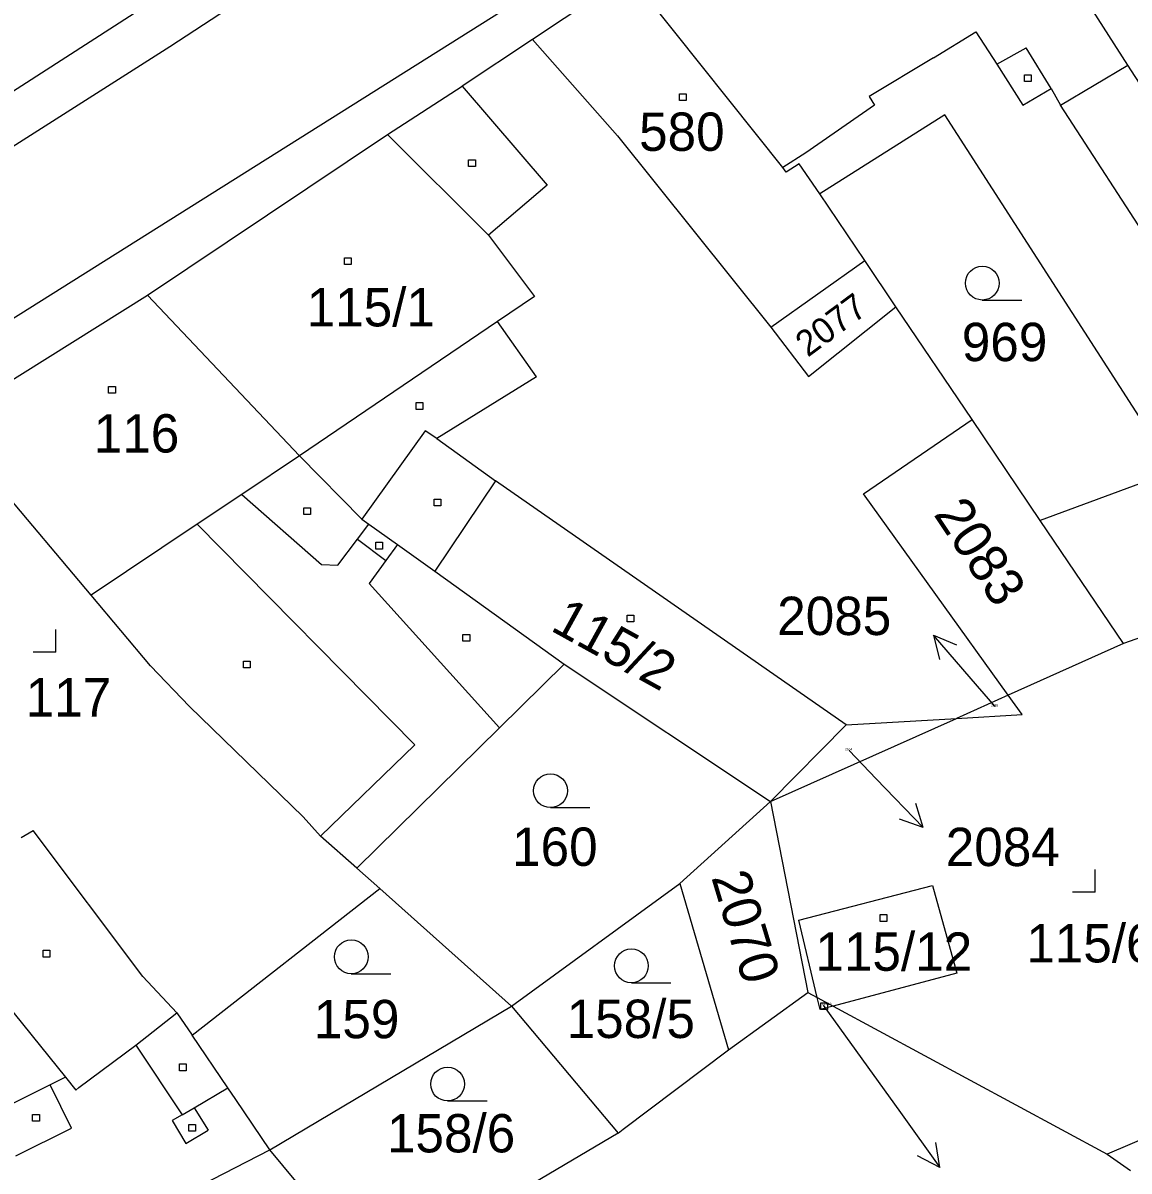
# Model space of a CAD drawing. Extents: x -711879 to -711361, y -1048782 to -1048177.
# Drawn here: x -711718.9 to -711669.9, y -1048619.6 to -1048568.8 of the extents above; entities that cross this region are included whole.
import ezdxf

# ---------------------------------------------------------------- set-up
doc = ezdxf.new("R2010")
doc.units = 0
for name, color, linetype in [('Vrstva 1', 7, 'Continuous'), ('Vrstva 13', 7, 'Continuous'), ('Vrstva 14', 7, 'Continuous'), ('Vrstva 15', 7, 'Continuous'), ('Vrstva 16', 7, 'Continuous'), ('Vrstva 2', 7, 'Continuous'), ('Vrstva 23', 7, 'Continuous'), ('Vrstva 25', 7, 'Continuous'), ('Vrstva 46', 7, 'Continuous')]:
    doc.layers.add(name, color=color, linetype=linetype)

msp = doc.modelspace()

# ---------------------------------------------------------------- linework, layer by layer
at = {"layer": 'Vrstva 1'}
for p, q in [((-711701.7, -1048560.4), (-711721.23, -1048572.99)), ((-711669.91, -1048570.62), (-711672.81, -1048566.11)), ((-711692.02, -1048566.63), (-711696.32, -1048569.48)), ((-711685.22, -1048575.16), (-711692.02, -1048566.63)), ((-711696.32, -1048569.48), (-711699.43, -1048571.55)), ((-711696.32, -1048569.48), (-711692.54, -1048573.75)), ((-711665.72, -1048577.15), (-711669.91, -1048570.62)), ((-711702.75, -1048573.69), (-711699.43, -1048571.55)), ((-711678.03, -1048572.83), (-711683.58, -1048576.33)), ((-711667.86, -1048588.61), (-711678.03, -1048572.83)), ((-711713.38, -1048580.81), (-711702.75, -1048573.69)), ((-711692.54, -1048573.75), (-711685.74, -1048582.24)), ((-711685.06, -1048575.36), (-711685.22, -1048575.16)), ((-711684.49, -1048574.99), (-711685.06, -1048575.36)), ((-711683.58, -1048576.33), (-711684.49, -1048574.99)), ((-711681.58, -1048579.28), (-711683.58, -1048576.33)), ((-711685.74, -1048582.24), (-711681.58, -1048579.28)), ((-711680.2, -1048581.33), (-711681.58, -1048579.28)), ((-711722.36, -1048586.43), (-711713.38, -1048580.81)), ((-711713.38, -1048580.81), (-711706.64, -1048587.93)), ((-711684.08, -1048584.42), (-711680.2, -1048581.33)), ((-711676.82, -1048586.33), (-711680.2, -1048581.33)), ((-711685.74, -1048582.24), (-711684.08, -1048584.42)), ((-711681.64, -1048589.62), (-711676.82, -1048586.33)), ((-711673.81, -1048590.81), (-711676.82, -1048586.33)), ((-711715.89, -1048594.11), (-711722.36, -1048586.43)), ((-711701.07, -1048586.83), (-711703.88, -1048590.74)), ((-711700.56, -1048587.17), (-711701.07, -1048586.83)), ((-711700.56, -1048587.17), (-711697.96, -1048589.04)), ((-711706.64, -1048587.93), (-711703.88, -1048590.74)), ((-711667.86, -1048588.61), (-711673.81, -1048590.81)), ((-711682.4, -1048599.86), (-711697.96, -1048589.04)), ((-711675.22, -1048598.54), (-711681.64, -1048589.62)), ((-711703.88, -1048590.74), (-711703.57, -1048590.96)), ((-711670.11, -1048596.26), (-711673.81, -1048590.81)), ((-711703.57, -1048590.96), (-711702.3, -1048591.87)), ((-711702.3, -1048591.87), (-711700.65, -1048593.05)), ((-711657.67, -1048591.88), (-711670.11, -1048596.26)), ((-711700.65, -1048593.05), (-711694.91, -1048597.17)), ((-711713.25, -1048597.25), (-711715.89, -1048594.11)), ((-711670.11, -1048596.26), (-711675.22, -1048598.54)), ((-711711.52, -1048599.04), (-711713.25, -1048597.25)), ((-711694.91, -1048597.17), (-711697.78, -1048599.99)), ((-711694.91, -1048597.17), (-711685.76, -1048603.26)), ((-711675.22, -1048598.54), (-711677.52, -1048599.58)), ((-711674.6, -1048599.4), (-711675.22, -1048598.54)), ((-711706.49, -1048603.94), (-711711.52, -1048599.04)), ((-711685.76, -1048603.26), (-711677.52, -1048599.58)), ((-711682.4, -1048599.86), (-711677.52, -1048599.58)), ((-711677.52, -1048599.58), (-711674.6, -1048599.4)), ((-711697.78, -1048599.99), (-711704.11, -1048606.21)), ((-711685.76, -1048603.26), (-711682.4, -1048599.86)), ((-711689.78, -1048606.89), (-711685.76, -1048603.26)), ((-711685.76, -1048603.26), (-711684.1, -1048611.72)), ((-711705.71, -1048604.79), (-711706.49, -1048603.94)), ((-711718.99, -1048604.85), (-711718.45, -1048604.54)), ((-711713.59, -1048611.01), (-711718.45, -1048604.54)), ((-711704.11, -1048606.21), (-711705.71, -1048604.79)), ((-711703.09, -1048607.12), (-711704.11, -1048606.21)), ((-711711.41, -1048613.62), (-711703.09, -1048607.12)), ((-711703.09, -1048607.12), (-711697.25, -1048612.33)), ((-711697.25, -1048612.33), (-711689.78, -1048606.89)), ((-711689.78, -1048606.89), (-711687.63, -1048614.26)), ((-711683.69, -1048611.94), (-711684.5, -1048608.51)), ((-711713.59, -1048611.01), (-711712.08, -1048612.63)), ((-711687.63, -1048614.26), (-711684.1, -1048611.72)), ((-711684.1, -1048611.72), (-711683.69, -1048611.94)), ((-711683.56, -1048612.48), (-711683.69, -1048611.94)), ((-711683.69, -1048611.94), (-711682.98, -1048612.33)), ((-711713.9, -1048614.06), (-711712.08, -1048612.63)), ((-711712.08, -1048612.63), (-711711.41, -1048613.62)), ((-711707.96, -1048618.7), (-711697.25, -1048612.33)), ((-711697.25, -1048612.33), (-711692.51, -1048617.95)), ((-711682.98, -1048612.33), (-711683.56, -1048612.48)), ((-711682.98, -1048612.33), (-711670.84, -1048618.89)), ((-711709.83, -1048615.95), (-711711.41, -1048613.62)), ((-711716.43, -1048615.94), (-711713.9, -1048614.06)), ((-711692.29, -1048617.78), (-711687.63, -1048614.26)), ((-711660.3, -1048614.41), (-711670.84, -1048618.89)), ((-711717.7, -1048615.82), (-711720.7, -1048617.31)), ((-711717.02, -1048615.48), (-711717.7, -1048615.82)), ((-711717.02, -1048615.48), (-711716.56, -1048616.05)), ((-711716.56, -1048616.05), (-711716.43, -1048615.94)), ((-711709.47, -1048616.47), (-711709.83, -1048615.95)), ((-711707.96, -1048618.7), (-711709.47, -1048616.47)), ((-711692.51, -1048617.95), (-711692.29, -1048617.78)), ((-711692.51, -1048617.95), (-711703.27, -1048624.31)), ((-711719.96, -1048624.83), (-711707.96, -1048618.7)), ((-711703.27, -1048624.31), (-711707.96, -1048618.7)), ((-711670.84, -1048618.89), (-711669.8, -1048619.61))]:
    msp.add_line(p, q, dxfattribs=at)
msp.add_lwpolyline([(-711684.5, -1048608.51), (-711678.58, -1048606.98), (-711677.5, -1048610.86), (-711682.98, -1048612.33)], dxfattribs=at)
at = {"layer": 'Vrstva 13'}
for p, q in [((-711675.8, -1048599.05), (-711676.58, -1048598.15)), ((-711682.28, -1048600.99), (-711681.07, -1048602.25)), ((-711683.42, -1048612.28), (-711680, -1048617.04))]:
    msp.add_line(p, q, dxfattribs=at)
at = {"layer": 'Vrstva 16'}
for p, q in [((-711676.58, -1048598.15), (-711678.541, -1048595.88)), ((-711678.541, -1048595.88), (-711678.266, -1048596.963)), ((-711678.541, -1048595.88), (-711677.509, -1048596.309)), ((-711681.07, -1048602.25), (-711678.993, -1048604.415)), ((-711678.993, -1048604.415), (-711679.324, -1048603.347)), ((-711678.993, -1048604.415), (-711680.046, -1048604.039)), ((-711680, -1048617.04), (-711678.25, -1048619.477)), ((-711678.25, -1048619.477), (-711678.427, -1048618.373)), ((-711678.25, -1048619.477), (-711679.239, -1048618.956))]:
    msp.add_line(p, q, dxfattribs=at)
at = {"layer": 'Vrstva 2'}
for p, q in [((-711712.4, -1048569.8), (-711692.52, -1048556.74)), ((-711687.47, -1048561.81), (-711745.53, -1048598.31)), ((-711678.53, -1048570.29), (-711676.66, -1048569.14)), ((-711676.66, -1048569.14), (-711675.72, -1048570.58)), ((-711736.24, -1048584.93), (-711712.4, -1048569.8)), ((-711675.72, -1048570.58), (-711674.43, -1048569.85)), ((-711673.31, -1048571.66), (-711674.43, -1048569.85)), ((-711678.53, -1048570.29), (-711681.39, -1048572.01)), ((-711675.72, -1048570.58), (-711674.57, -1048572.4)), ((-711672.9, -1048572.39), (-711669.91, -1048570.62)), ((-711699.43, -1048571.55), (-711695.66, -1048575.94)), ((-711681.39, -1048572.01), (-711681.15, -1048572.39)), ((-711674.57, -1048572.4), (-711673.31, -1048571.66)), ((-711673.31, -1048571.66), (-711672.9, -1048572.39)), ((-711681.15, -1048572.39), (-711684.19, -1048574.5)), ((-711668.28, -1048579.53), (-711672.9, -1048572.39)), ((-711698.26, -1048578.16), (-711702.75, -1048573.69)), ((-711684.19, -1048574.5), (-711685.22, -1048575.16)), ((-711695.66, -1048575.94), (-711698.26, -1048578.16)), ((-711698.26, -1048578.16), (-711696.23, -1048580.87)), ((-711696.23, -1048580.87), (-711697.86, -1048581.98)), ((-711697.86, -1048581.98), (-711706.64, -1048587.93)), ((-711696.14, -1048584.43), (-711697.86, -1048581.98)), ((-711696.14, -1048584.43), (-711700.56, -1048587.17)), ((-711706.64, -1048587.93), (-711709.21, -1048589.65)), ((-711697.96, -1048589.04), (-711700.65, -1048593.05)), ((-711709.21, -1048589.65), (-711711.19, -1048590.97)), ((-711709.21, -1048589.65), (-711705.67, -1048592.75)), ((-711711.19, -1048590.97), (-711715.89, -1048594.11)), ((-711701.54, -1048600.75), (-711711.19, -1048590.97)), ((-711704.08, -1048591.63), (-711703.57, -1048590.96)), ((-711704.94, -1048592.78), (-711704.08, -1048591.63)), ((-711704.08, -1048591.63), (-711702.82, -1048592.58)), ((-711702.3, -1048591.87), (-711702.82, -1048592.58)), ((-711705.67, -1048592.75), (-711704.94, -1048592.78)), ((-711702.82, -1048592.58), (-711703.56, -1048593.59)), ((-711703.56, -1048593.59), (-711697.78, -1048599.99)), ((-711705.71, -1048604.79), (-711701.54, -1048600.75)), ((-711721.21, -1048610.29), (-711717.02, -1048615.48)), ((-711713.9, -1048614.06), (-711711.85, -1048617.14)), ((-711716.76, -1048617.74), (-711717.7, -1048615.82)), ((-711711.32, -1048616.83), (-711709.83, -1048615.95)), ((-711711.85, -1048617.14), (-711711.32, -1048616.83)), ((-711711.32, -1048616.83), (-711710.7, -1048617.82)), ((-711711.85, -1048617.14), (-711712.29, -1048617.39)), ((-711712.29, -1048617.39), (-711711.69, -1048618.41)), ((-711719.23, -1048618.96), (-711716.76, -1048617.74)), ((-711711.69, -1048618.41), (-711710.7, -1048617.82))]:
    msp.add_line(p, q, dxfattribs=at)
at = {"layer": 'Vrstva 23'}
for p, q in [((-711676.37, -1048581.03), (-711674.62, -1048581.03)), ((-711717.45, -1048596.64), (-711717.45, -1048595.64)), ((-711717.45, -1048596.64), (-711718.45, -1048596.64)), ((-711695.52, -1048603.53), (-711693.77, -1048603.53)), ((-711671.37, -1048607.27), (-711671.37, -1048606.27)), ((-711671.37, -1048607.27), (-711672.37, -1048607.27)), ((-711704.35, -1048610.89), (-711702.6, -1048610.89)), ((-711691.93, -1048611.29), (-711690.18, -1048611.29)), ((-711700.08, -1048616.53), (-711698.33, -1048616.53))]:
    msp.add_line(p, q, dxfattribs=at)
for centre in [(-711676.37, -1048580.28), (-711695.52, -1048602.78), (-711704.35, -1048610.14), (-711691.93, -1048610.54), (-711700.08, -1048615.78)]:
    msp.add_circle(centre, 0.75, dxfattribs=at)
at = {"layer": 'Vrstva 25'}
for p, q in [((-711674.5, -1048571.05), (-711674.2, -1048571.05)), ((-711674.5, -1048571.35), (-711674.5, -1048571.05)), ((-711674.2, -1048571.05), (-711674.2, -1048571.35)), ((-711674.2, -1048571.35), (-711674.5, -1048571.35)), ((-711689.8, -1048571.89), (-711689.5, -1048571.89)), ((-711689.8, -1048572.19), (-711689.8, -1048571.89)), ((-711689.5, -1048571.89), (-711689.5, -1048572.19)), ((-711689.5, -1048572.19), (-711689.8, -1048572.19)), ((-711699.15, -1048574.82), (-711698.85, -1048574.82)), ((-711699.15, -1048575.12), (-711699.15, -1048574.82)), ((-711698.85, -1048575.12), (-711699.15, -1048575.12)), ((-711698.85, -1048574.82), (-711698.85, -1048575.12)), ((-711704.65, -1048579.16), (-711704.35, -1048579.16)), ((-711704.65, -1048579.46), (-711704.65, -1048579.16)), ((-711704.35, -1048579.16), (-711704.35, -1048579.46)), ((-711704.35, -1048579.46), (-711704.65, -1048579.46)), ((-711715.11, -1048584.86), (-711714.81, -1048584.86)), ((-711715.11, -1048585.16), (-711715.11, -1048584.86)), ((-711714.81, -1048585.16), (-711715.11, -1048585.16)), ((-711714.81, -1048584.86), (-711714.81, -1048585.16)), ((-711701.48, -1048585.58), (-711701.18, -1048585.58)), ((-711701.48, -1048585.88), (-711701.48, -1048585.58)), ((-711701.18, -1048585.58), (-711701.18, -1048585.88)), ((-711701.18, -1048585.88), (-711701.48, -1048585.88)), ((-711700.68, -1048589.86), (-711700.38, -1048589.86)), ((-711700.68, -1048590.16), (-711700.68, -1048589.86)), ((-711700.38, -1048589.86), (-711700.38, -1048590.16)), ((-711706.46, -1048590.24), (-711706.16, -1048590.24)), ((-711706.46, -1048590.54), (-711706.46, -1048590.24)), ((-711706.16, -1048590.24), (-711706.16, -1048590.54)), ((-711700.38, -1048590.16), (-711700.68, -1048590.16)), ((-711706.16, -1048590.54), (-711706.46, -1048590.54)), ((-711703.26, -1048591.77), (-711702.96, -1048591.77)), ((-711703.26, -1048592.07), (-711703.26, -1048591.77)), ((-711702.96, -1048591.77), (-711702.96, -1048592.07)), ((-711702.96, -1048592.07), (-711703.26, -1048592.07)), ((-711692.12, -1048595), (-711691.82, -1048595)), ((-711692.12, -1048595.3), (-711692.12, -1048595)), ((-711691.82, -1048595), (-711691.82, -1048595.3)), ((-711691.82, -1048595.3), (-711692.12, -1048595.3)), ((-711699.4, -1048595.85), (-711699.1, -1048595.85)), ((-711699.4, -1048596.15), (-711699.4, -1048595.85)), ((-711699.1, -1048595.85), (-711699.1, -1048596.15)), ((-711699.1, -1048596.15), (-711699.4, -1048596.15)), ((-711709.13, -1048597.04), (-711708.83, -1048597.04)), ((-711709.13, -1048597.34), (-711709.13, -1048597.04)), ((-711708.83, -1048597.04), (-711708.83, -1048597.34)), ((-711708.83, -1048597.34), (-711709.13, -1048597.34)), ((-711680.9, -1048608.27), (-711680.6, -1048608.27)), ((-711680.9, -1048608.57), (-711680.9, -1048608.27)), ((-711680.6, -1048608.57), (-711680.9, -1048608.57)), ((-711680.6, -1048608.27), (-711680.6, -1048608.57)), ((-711718.02, -1048609.85), (-711717.72, -1048609.85)), ((-711718.02, -1048610.15), (-711718.02, -1048609.85)), ((-711717.72, -1048610.15), (-711718.02, -1048610.15)), ((-711717.72, -1048609.85), (-711717.72, -1048610.15)), ((-711683.53, -1048612.18), (-711683.23, -1048612.18)), ((-711683.53, -1048612.48), (-711683.53, -1048612.18)), ((-711683.23, -1048612.18), (-711683.23, -1048612.48)), ((-711683.23, -1048612.48), (-711683.53, -1048612.48)), ((-711711.97, -1048614.89), (-711711.67, -1048614.89)), ((-711711.97, -1048615.19), (-711711.97, -1048614.89)), ((-711711.67, -1048615.19), (-711711.97, -1048615.19)), ((-711711.67, -1048614.89), (-711711.67, -1048615.19)), ((-711718.48, -1048617.13), (-711718.18, -1048617.13)), ((-711718.48, -1048617.43), (-711718.48, -1048617.13)), ((-711718.18, -1048617.13), (-711718.18, -1048617.43)), ((-711718.18, -1048617.43), (-711718.48, -1048617.43)), ((-711711.56, -1048617.57), (-711711.26, -1048617.57)), ((-711711.56, -1048617.87), (-711711.56, -1048617.57)), ((-711711.26, -1048617.87), (-711711.56, -1048617.87)), ((-711711.26, -1048617.57), (-711711.26, -1048617.87))]:
    msp.add_line(p, q, dxfattribs=at)
at = {"layer": 'Vrstva 46'}
for p, q in [((-711678.53, -1048570.29), (-711678.53, -1048570.29)), ((-711675.72, -1048570.58), (-711675.72, -1048570.58)), ((-711699.43, -1048571.55), (-711699.43, -1048571.55)), ((-711672.9, -1048572.39), (-711672.9, -1048572.39)), ((-711678.03, -1048572.83), (-711678.03, -1048572.83)), ((-711702.75, -1048573.69), (-711702.75, -1048573.69)), ((-711692.54, -1048573.75), (-711692.54, -1048573.75)), ((-711684.19, -1048574.5), (-711684.19, -1048574.5)), ((-711685.06, -1048575.36), (-711685.06, -1048575.36)), ((-711698.26, -1048578.16), (-711698.26, -1048578.16)), ((-711713.38, -1048580.81), (-711713.38, -1048580.81)), ((-711696.23, -1048580.87), (-711696.23, -1048580.87)), ((-711696.14, -1048584.43), (-711696.14, -1048584.43)), ((-711700.56, -1048587.17), (-711700.56, -1048587.17)), ((-711697.96, -1048589.04), (-711697.96, -1048589.04)), ((-711681.64, -1048589.62), (-711681.64, -1048589.62)), ((-711674.28, -1048590.1), (-711674.28, -1048590.1)), ((-711673.81, -1048590.81), (-711673.81, -1048590.81)), ((-711670.11, -1048596.26), (-711670.11, -1048596.26)), ((-711713.25, -1048597.25), (-711713.25, -1048597.25)), ((-711675.22, -1048598.54), (-711675.22, -1048598.54)), ((-711711.52, -1048599.04), (-711711.52, -1048599.04)), ((-711677.52, -1048599.58), (-711677.52, -1048599.58)), ((-711674.6, -1048599.4), (-711674.6, -1048599.4)), ((-711682.4, -1048599.86), (-711682.4, -1048599.86)), ((-711685.76, -1048603.26), (-711685.76, -1048603.26)), ((-711706.49, -1048603.94), (-711706.49, -1048603.94)), ((-711718.45, -1048604.54), (-711718.45, -1048604.54)), ((-711705.71, -1048604.79), (-711705.71, -1048604.79)), ((-711703.09, -1048607.12), (-711703.09, -1048607.12)), ((-711689.78, -1048606.89), (-711689.78, -1048606.89)), ((-711713.59, -1048611.01), (-711713.59, -1048611.01)), ((-711684.1, -1048611.72), (-711684.1, -1048611.72)), ((-711683.69, -1048611.94), (-711683.69, -1048611.94)), ((-711712.08, -1048612.63), (-711712.08, -1048612.63)), ((-711697.25, -1048612.33), (-711697.25, -1048612.33)), ((-711682.98, -1048612.33), (-711682.98, -1048612.33)), ((-711711.41, -1048613.62), (-711711.41, -1048613.62)), ((-711687.63, -1048614.26), (-711687.63, -1048614.26)), ((-711717.02, -1048615.48), (-711717.02, -1048615.48)), ((-711716.56, -1048616.05), (-711716.56, -1048616.05)), ((-711716.43, -1048615.94), (-711716.43, -1048615.94)), ((-711709.47, -1048616.47), (-711709.47, -1048616.47)), ((-711716.76, -1048617.74), (-711716.76, -1048617.74)), ((-711692.29, -1048617.78), (-711692.29, -1048617.78)), ((-711692.51, -1048617.95), (-711692.51, -1048617.95)), ((-711707.96, -1048618.7), (-711707.96, -1048618.7)), ((-711670.84, -1048618.89), (-711670.84, -1048618.89))]:
    msp.add_line(p, q, dxfattribs=at)

# ---------------------------------------------------------------- texts
at = {"layer": 'Vrstva 14'}
for s, height, rotation, p in [('2077', 1.14, 36.511, (-711684.108, -1048583.592)), ('2083', 1.7, 303.5589, (-711678.558, -1048590.525)), ('2070', 1.7, 286.7937, (-711688.394, -1048606.615))]:
    msp.add_text(s, height=height, rotation=rotation, dxfattribs=at).set_placement(p)
for s, height, p in [('969', 1.7, (-711677.28, -1048583.74)), ('2085', 0.1, (-711675.974, -1048599.05)), ('2084', 0.1, (-711682.451, -1048600.99)), ('160', 1.7, (-711697.22, -1048606.11)), ('159', 1.7, (-711706.01, -1048613.75)), ('158/5', 1.7, (-711694.8, -1048613.74)), ('158/6', 1.7, (-711702.77, -1048618.81))]:
    msp.add_text(s, height=height, dxfattribs=at).set_placement(p)
at = {"layer": 'Vrstva 15'}
for s, height, p in [('580', 1.7, (-711691.59, -1048574.42)), ('115/1', 1.7, (-711706.33, -1048582.2)), ('116', 1.7, (-711715.77, -1048587.79)), ('117', 1.7, (-711718.79, -1048599.49)), ('115/6', 1.7, (-711674.42, -1048610.39)), ('115/12', 1.7, (-711683.77, -1048610.76)), ('115/13', 0.1, (-711683.48, -1048612.28))]:
    msp.add_text(s, height=height, dxfattribs=at).set_placement(p)
msp.add_text('115/2', height=1.7, rotation=331.0963, dxfattribs=at).set_placement((-711695.57, -1048595.65))
at = {"layer": 'Vrstva 16'}
for s, p in [('2085', (-711685.464, -1048595.88)), ('2084', (-711677.99, -1048606.12))]:
    msp.add_text(s, height=1.7, dxfattribs=at).set_placement(p)

doc.saveas('drawing.dxf')
